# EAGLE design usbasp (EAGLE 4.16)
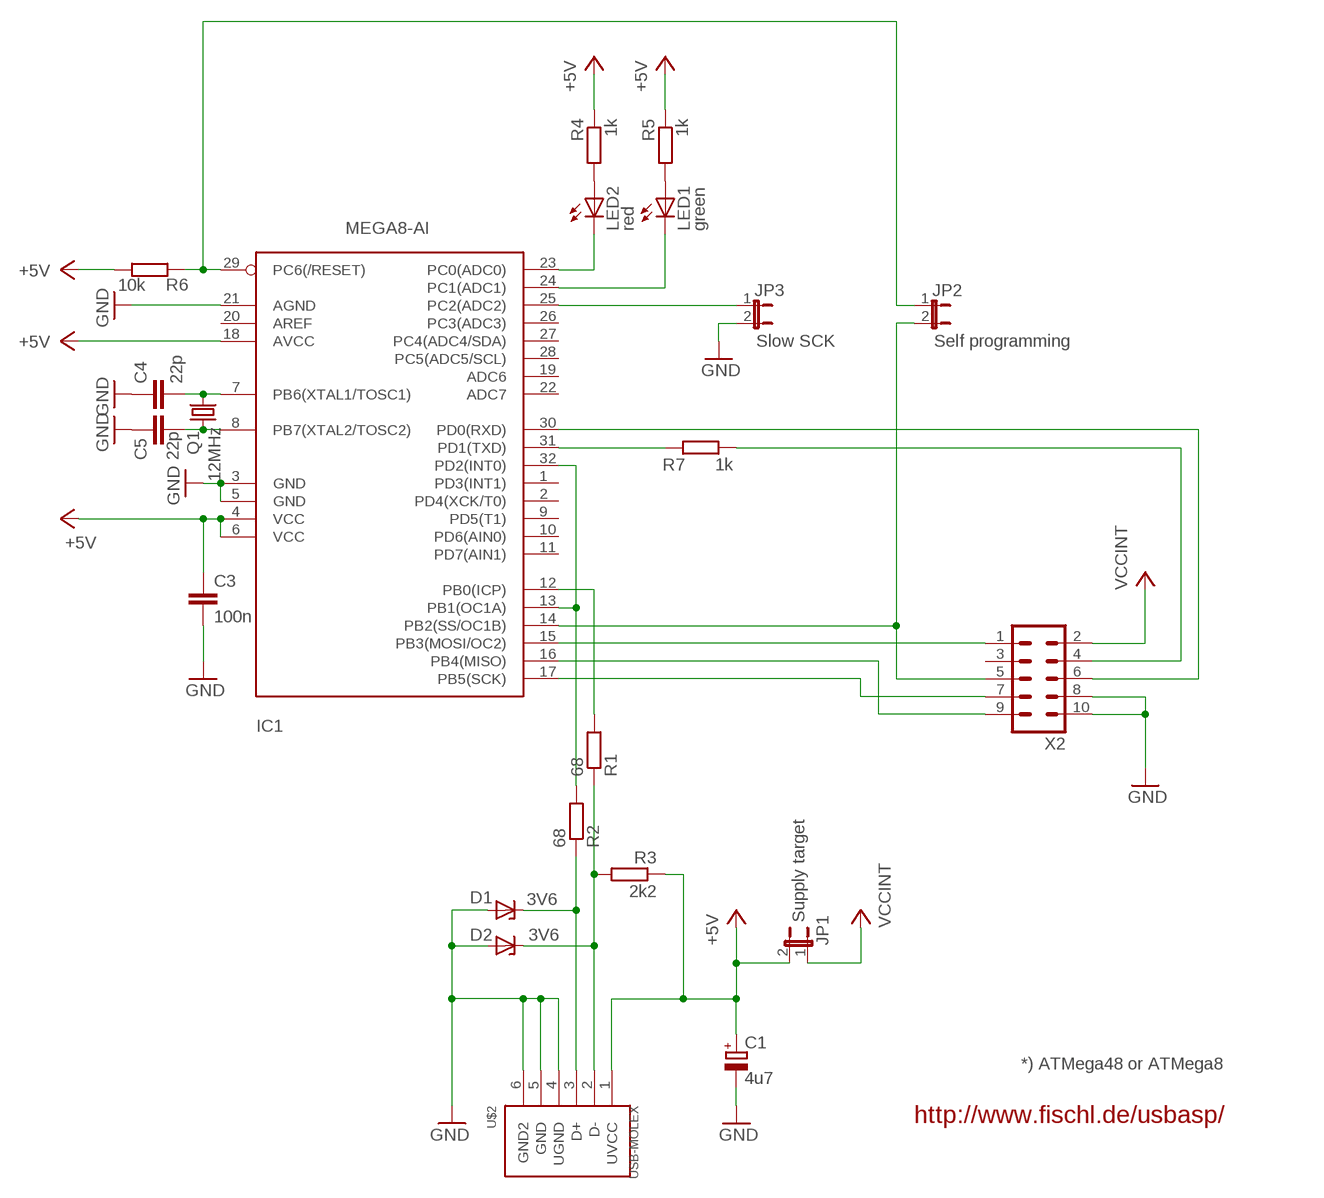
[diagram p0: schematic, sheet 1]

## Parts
C1  4u7  CPOL-EUE2.5-5  [E2,5-5]
C3  100n  C-EUC0805  [C0805]
C4  22p  C-EUC0603  [C0603]
C5  22p  C-EUC0603  [C0603]
D1  3V6  ZENER-DIODEZD-7.5  [ZDIO-7.5]
D2  3V6  ZENER-DIODEZD-7.5  [ZDIO-7.5]
IC1  MEGA8-AI  [TQFP32-08]
JP1  Supply target  JP1E  [JP1]
JP2  Self programming  JP1E  [JP1]
JP3  Slow SCK  JP1E  [JP1]
LED1  green  LEDCHIPLED_1206  [CHIPLED_1206]
LED2  red  LEDCHIPLED_1206  [CHIPLED_1206]
Q1  12MHz  CRYTALHC49S  [HC49/S]
R1  68  R-EU_M0805  [M0805]
R2  68  R-EU_M0805  [M0805]
R3  2k2  R-EU_M0805  [M0805]
R4  1k  R-EU_M0805  [M0805]
R5  1k  R-EU_M0805  [M0805]
R6  10k  R-EU_M0805  [M0805]
R7  1k  R-EU_M0805  [M0805]
U$2  USB-MOLEX  [USB-MOLEX]
X2  ML10  [ML10]

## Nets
+5V: C1.+ C3.1 IC1.4(VCC) IC1.6(VCC) IC1.18(AVCC) JP1.2 R3.1 R4.1 R5.1 R6.1 U$2.1(UVCC)
GND: C1.- C3.2 C4.1 C5.1 D1.A D2.A IC1.3(GND) IC1.5(GND) IC1.21(AGND) JP3.2 U$2.4(UGND) U$2.5(GND) U$2.6(GND2) X2.8 X2.10
N$1: IC1.29(PC6(/RESET)) JP2.1 R6.2
N$2: IC1.14(PB2(SS/OC1B)) JP2.2 X2.5
N$3: IC1.15(PB3(MOSI/OC2)) X2.1
N$4: IC1.17(PB5(SCK)) X2.7
N$6: IC1.16(PB4(MISO)) X2.9
N$7: IC1.13(PB1(OC1A)) IC1.32(PD2(INT0)) R2.2
N$9: IC1.31(PD1(TXD)) R7.2
N$10: R7.1 X2.4
N$11: IC1.30(PD0(RXD)) X2.6
N$12: IC1.25(PC2(ADC2)) JP3.1
N$13: LED2.A R4.2
N$14: IC1.23(PC0(ADC0)) LED2.C
N$15: IC1.24(PC1(ADC1)) LED1.C
N$16: IC1.12(PB0(ICP)) R1.2
N$17: D2.C R1.1 R3.2 U$2.2(D-)
N$18: D1.C R2.1 U$2.3(D+)
N$22: C4.2 IC1.7(PB6(XTAL1/TOSC1)) Q1.2
N$23: C5.2 IC1.8(PB7(XTAL2/TOSC2)) Q1.1
N$25: LED1.A R5.2
VCCINT: JP1.1 X2.2
Unconnected: IC1.1(PD3(INT1)) IC1.2(PD4(XCK/T0)) IC1.9(PD5(T1)) IC1.10(PD6(AIN0)) IC1.11(PD7(AIN1)) IC1.19(ADC6) IC1.20(AREF) IC1.22(ADC7) IC1.26(PC3(ADC3)) IC1.27(PC4(ADC4/SDA)) IC1.28(PC5(ADC5/SCL)) X2.3

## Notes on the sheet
- *) ATMega48 or ATMega8
- http://www.fischl.de/usbasp/

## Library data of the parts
C1 = rcl:CPOL-EU: POLARIZED CAPACITOR, European symbol
C3-C5 = rcl:C-EU: CAPACITOR, European symbol
D1 D2 = diode:ZENER-DIODE: Z-Diode
IC1 = atmel:MEGA8: MICROCONTROLLER 8 Kbytes FLASH 1 kbytes SRAM 512 bytes EEPROM USART 6-channel 10 bit ADC 2-channel 8 bit ADC Source: avr.lbr
JP1-JP3 = jumper:JP1E: JUMPER
LED1 LED2 = led:LED: LED
Q1 = crystal:CRYTAL: CRYSTAL
R1-R7 = rcl:R-EU_: RESISTOR, European symbol
U$2 = usb:USB-MOLEX
X2 = con-harting-ml:ML10: HARTING

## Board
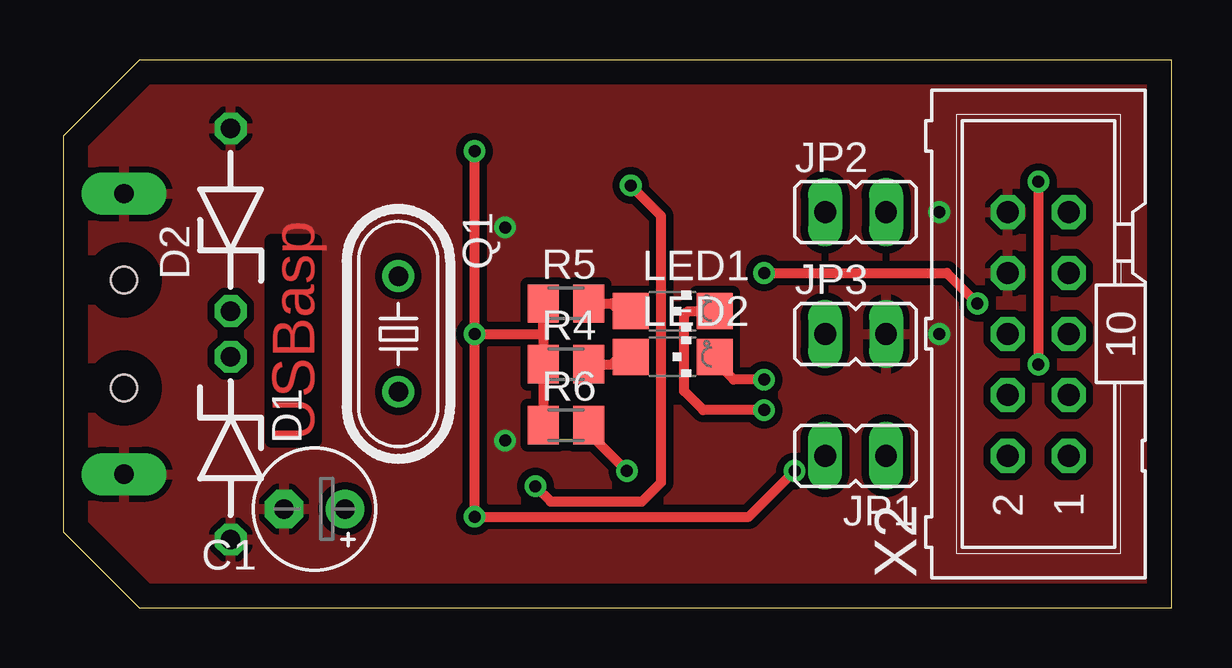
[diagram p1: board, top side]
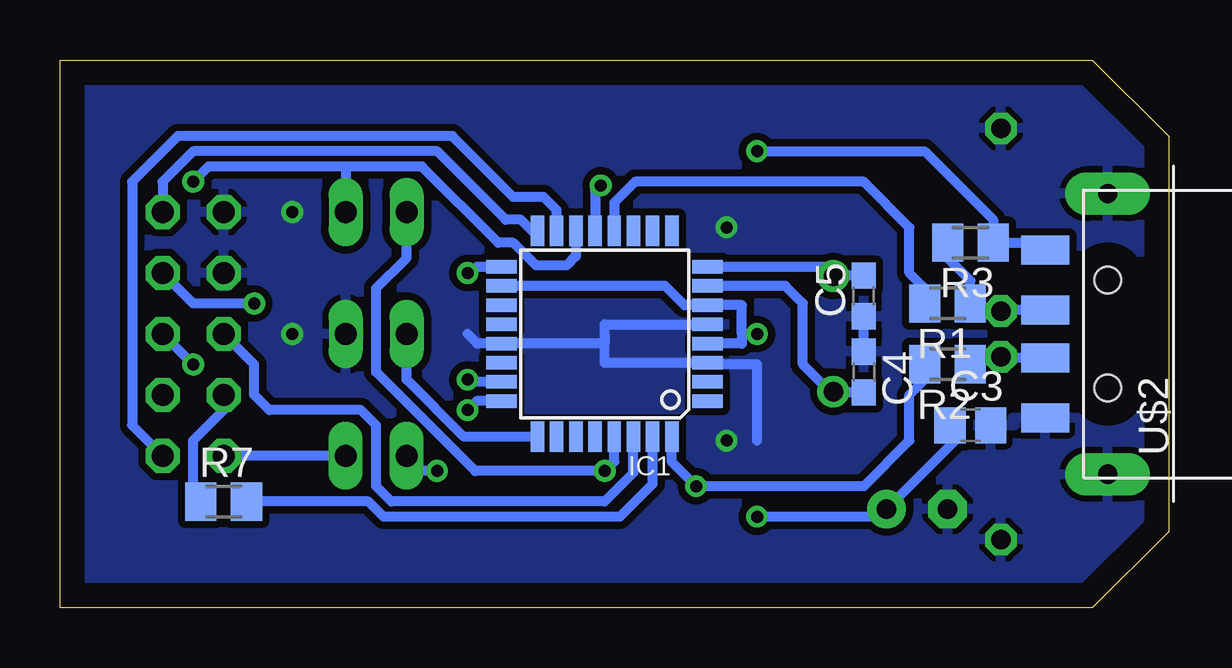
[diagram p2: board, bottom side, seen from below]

Size 46.19 x 22.85 mm. Coordinates in mm from the lower left corner, seen from the top.
Outline: 46.19,0 46.19,22.85 3.17,22.85 0,19.68 0,3.17 3.17,0 46.19,0
Copper layers (1*16): Top 0.035mm / dielectric 1.5mm / Bottom 0.035mm
Design rules "default": minimum track width 10mil, minimum drill 15mil, track to track 8mil, track to pad 8mil, pad to pad 8mil, via to via 8mil, smd to smd 8mil, copper to edge 40mil, drill to drill 8mil, minimum pad ring 10mil, minimum via ring 8mil, stop-mask expansion 4mil, vias tented up to drill 0mil, thermal gap 10mil
bRestrict: area 4.1,8.6 to 6.3,9.8; area 6.7,8.6 to 8.3,9.2

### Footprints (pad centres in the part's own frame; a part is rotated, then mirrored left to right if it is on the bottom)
E2,5-5 = drill 0.813 pad 1.6 round: + -1.27,0 | drill 0.813 pad 1.6 octagon: - 1.27,0
C0805 = smd 1.3 x 1.5: 1 -0.85,0; 2 0.85,0
C0603 = smd 1.1 x 1: 1 -0.85,0; 2 0.85,0
ZDIO-7.5 = drill 0.813 octagon: A 3.81,0; C -3.81,0
TQFP32-08 = smd 1.27 x 0.559: 1 -4.293,2.8; 2 -4.293,2; 3 -4.293,1.2; 4 -4.293,0.4; 5 -4.293,-0.4; 6 -4.293,-1.2; 7 -4.293,-2; 8 -4.293,-2.8; 17 4.293,-2.8; 18 4.293,-2; 19 4.293,-1.2; 20 4.293,-0.4; 21 4.293,0.4; 22 4.293,1.2; 23 4.293,2; 24 4.293,2.8 | smd 0.559 x 1.27: 9 -2.8,-4.293; 10 -2,-4.293; 11 -1.2,-4.293; 12 -0.4,-4.293; 13 0.4,-4.293; 14 1.2,-4.293; 15 2,-4.293; 16 2.8,-4.293; 25 2.8,4.293; 26 2,4.293; 27 1.2,4.293; 28 0.4,4.293; 29 -0.4,4.293; 30 -1.2,4.293; 31 -2,4.293; 32 -2.8,4.293
JP1 = drill 0.914 long: 1 0,-1.27; 2 0,1.27
CHIPLED_1206 = smd 1.5 x 1.5: A 0,-1.75; C 0,1.75
HC49/S = drill 0.813 round: 1 -2.413,0; 2 2.413,0
M0805 = smd 1.3 x 1.6: 1 -0.95,0; 2 0.95,0
USB-MOLEX = smd 1.2 x 2: 1 3.5,2.6; 2 1,2.6; 3 -1,2.6; 4 -3.5,2.6 | drill 0.8 pad 1.778 long: 5 5.85,0; 6 -5.85,0 | hole 1.1: -2.25,0; 2.25,0
ML10 = drill 0.914 octagon: 1 -5.08,-1.27; 2 -5.08,1.27; 3 -2.54,-1.27; 4 -2.54,1.27; 5 0,-1.27; 6 0,1.27; 7 2.54,-1.27; 8 2.54,1.27; 9 5.08,-1.27; 10 5.08,1.27

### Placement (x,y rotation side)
C1  10.48,4.12 180 top
C3  8.26,7.61 0 bottom
C4  12.7,9.84 270 bottom
C5  12.7,13.01 90 bottom
D1  6.98,6.66 270 top
D2  6.98,16.19 90 top
IC1  23.5,11.43 180 bottom
JP1  33.02,6.34 90 top
JP2  33.02,16.5 270 top
JP3  33.02,11.43 270 top
LED1  25.4,12.38 270 top
LED2  25.4,10.47 270 top
Q1  13.97,11.43 270 top
R1  9.21,12.7 180 bottom
R2  9.21,10.16 180 bottom
R3  8.26,15.24 180 bottom
R4  20.96,10.16 0 top
R5  20.96,12.7 0 top
R6  20.96,7.61 0 top
R7  39.37,4.44 0 bottom
U$2  2.54,11.43 90 bottom
X2  40.64,11.43 90 top

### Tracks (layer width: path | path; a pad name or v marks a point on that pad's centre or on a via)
+5V  (via drill 0.5)
  Top 0.406: 20.01,11.43 R4.1 20.32,10.16 20.01,9.84 R6.1 | 20.01,11.43 R5.1 | v17.15,11.43 20.01,11.43 | v17.15,11.43 v17.15,3.8 28.58,3.8 v30.48,5.71 | v17.15,11.43 v17.15,19.05
  Bottom 0.406: IC1.4 17.78,11.03 17.78,11.43 | 17.78,11.43 17.78,12.62 IC1.6 20.18,12.62 20.98,13.43 IC1.18 | 9.53,7.61 C3.1 9.11,7.4 9.21,7.3 8.89,6.98 C1.+ 12.06,3.8 v17.15,3.8 | v17.15,11.43 17.78,11.43 | JP1.2 31.12,5.71 v30.48,5.71 | v17.15,19.05 10.16,19.05 7.3,16.19 R3.1 5.08,15.24 5.14,15.18 U$2.1
GND  (via drill 0.5)
  Bottom 0.406: IC1.5 23.5,11.83 23.5,11.43 | 23.5,11.43 23.5,11.03 IC1.21 28.81,11.03 29.21,11.43 | 23.5,11.43 23.5,10.23 IC1.3 19.2,10.16 17.15,10.16 17.15,6.98 | C4.1 C5.1
  other vias: 18.42,15.87 18.42,6.98 36.51,16.5 36.51,11.43
  pour Bottom (isolate 0.305): -0.95,23.49 -0.95,-0.64 47.31,-0.64 47.31,23.49
  pour Top (isolate 0.305): -0.95,23.49 -0.95,-0.64 47.31,-0.64 47.31,23.49
N$1  (via drill 0.5)
  Top 0.406: R6.2 21.91,7.3 v23.5,5.71
  Bottom 0.406: JP2.1 31.75,14.6 33.02,13.33 33.02,9.84 28.89,5.71 v23.5,5.71 23.1,6.11 IC1.29
N$2  (via drill 0.5)
  Top 0.406: v40.64,17.78 v40.64,10.16
  Bottom 0.406: IC1.14 24.7,14.67 25.08,14.28 26.35,14.28 27.31,15.24 27.94,15.24 31.12,18.41 34.29,18.41 | 34.29,18.41 JP2.2 | 34.29,18.41 40,18.41 v40.64,17.78 | v40.64,10.16 X2.5
N$3
  Bottom 0.406: IC1.15 25.5,16.6 26.04,17.14 27.31,17.14 29.85,19.68 41.27,19.68 43.18,17.78 43.18,7.61 X2.1
N$4  (via drill 0.5)
  Top 0.406: v29.21,13.96 36.83,13.96 v38.1,12.7
  Bottom 0.406: IC1.17 28.84,14.23 v29.21,13.96 | X2.7 40.64,12.7 v38.1,12.7
N$6
  Bottom 0.406: IC1.16 26.52,15.72 26.99,16.19 27.62,16.19 30.48,19.05 40.64,19.05 41.91,17.78 X2.9
N$7  (via drill 0.5)
  Top 0.406: v23.65,17.62 24.92,16.35 24.92,5.23 24.13,4.44 20.32,4.44 v19.69,5.08
  Bottom 0.406: IC1.32 20.7,6.08 v19.69,5.08 12.7,5.08 10.79,6.98 10.79,8.88 10.16,9.52 R2.2 | IC1.13 23.9,17.38 v23.65,17.62
N$9
  Bottom 0.406: IC1.31 21.5,5.17 22.86,3.8 32.7,3.8 33.34,4.44 R7.2
N$10
  Bottom 0.406: X2.4 39.37,8.25 40.64,6.98 40.64,4.44 R7.1
N$11
  Bottom 0.406: IC1.30 22.3,5.64 23.5,4.44 32.38,4.44 33.02,5.08 33.02,7.61 33.66,8.25 37.46,8.25 38.1,8.88 38.1,10.16 X2.6
N$12
  Bottom 0.406: 26.3,6.98 IC1.25 29.36,7.13 31.75,9.52 JP3.1
N$13
  Top 0.406: LED2.A 23.65,10.63 23.5,10.79 22.86,10.16 R4.2
N$14  (via drill 0.5)
  Top 0.406: LED2.C 27.15,10.31 27.94,9.52 v29.21,9.52
  Bottom 0.406: IC1.23 29.12,9.43 v29.21,9.52
N$15  (via drill 0.5)
  Top 0.406: LED1.C 26.04,12.38 25.88,12.22 25.88,9.04 26.67,8.25 v29.21,8.25
  Bottom 0.406: IC1.24 28.84,8.62 v29.21,8.25
N$16
  Bottom 0.406: IC1.12 23.1,16.91 22.23,17.78 12.7,17.78 10.79,15.87 10.79,13.96 10.16,13.33 R1.2
N$17
  Bottom 0.406: 8.89,15.24 R3.2 9.21,14.6 8.26,13.65 R1.1 8.26,12.38 D2.C 6.98,12.43 U$2.2
N$18
  Bottom 0.406: U$2.3 6.98,10.43 D1.C 8.26,10.47 R2.1
N$22
  Bottom 0.406: IC1.7 15.97,13.43 15.24,12.7 15.24,10.16 13.97,8.88 | 13.97,8.88 Q1.2 | C4.2 13.97,8.99 13.97,8.88
N$23
  Bottom 0.406: IC1.8 14.23,14.23 13.97,13.96 Q1.1 | Q1.1 13.97,13.65 | C5.2 13.97,13.86 Q1.1
N$25
  Top 0.406: LED1.A 23.65,12.21 23.5,12.06 22.86,12.7 R5.2
VCCINT
  Bottom 0.406: JP1.1 X2.2

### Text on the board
Top: USBasp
